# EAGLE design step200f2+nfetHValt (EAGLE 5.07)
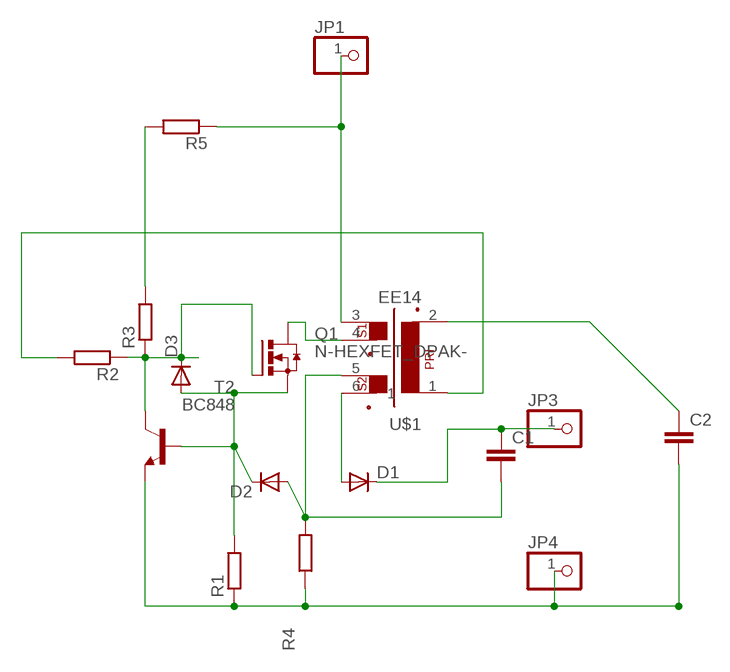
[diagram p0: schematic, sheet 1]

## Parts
C1  C-EU025-025X050  [C025-025X050]
C2  C-EUC0805  [C0805]
D1  DIODE-SMA-DO214  [SMA-DO214AC]
D2  DIODE-MINIMELF  [MINIMELF]
D3  DIODE-MINIMELF  [MINIMELF]
JP1  PINHD-1X11MM6  [1X1MM8]
JP3  PINHD-1X11MM6  [1X1MM8]
JP4  PINHD-1X11MM6  [1X1MM8]
Q1  N-HEXFET_DPAK-  [TO252]
R1  R-EU_R1206  [R1206]
R2  R-EU_R0805  [R0805]
R3  R-EU_R1206  [R1206]
R4  R-EU_R0805  [R0805]
R5  R-EU_R1206  [R1206]
T2  BC848  [SOT23]
U$1  EE14  [EE14]

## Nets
A: D1.A U$1.6
B1C2: D3.C Q1.1(G) R2.1 R3.1 T2.C
C1: Q1.3(D) U$1.4
EB: D2.C D3.A Q1.2(S) R1.2 T2.B
N$1: R3.2 R5.2
N$4: R2.2 U$1.1
N$6: C2.1 U$1.2
NDOT: C1.2 D2.A R4.2 U$1.5
V+: JP1.1 R5.1 U$1.3
V-: C2.2 JP4.1 R1.1 R4.1 T2.E
VOUT+: C1.1 D1.K(C) JP3.1

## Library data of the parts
C1 C2 = rcl:C-EU: CAPACITOR, European symbol
D1-D3 = diode:DIODE-: DIODE
JP1 JP3 JP4 = pinhead:PINHD-1X1: PIN HEADER
Q1 = transistor-power:N-HEXFET_?-*: HEXFET® Power MOSFET
R1-R5 = rcl:R-EU_: RESISTOR, European symbol
T2 = transistor:BC848: NPN TRANSISTOR
U$1 = trafo:EE14

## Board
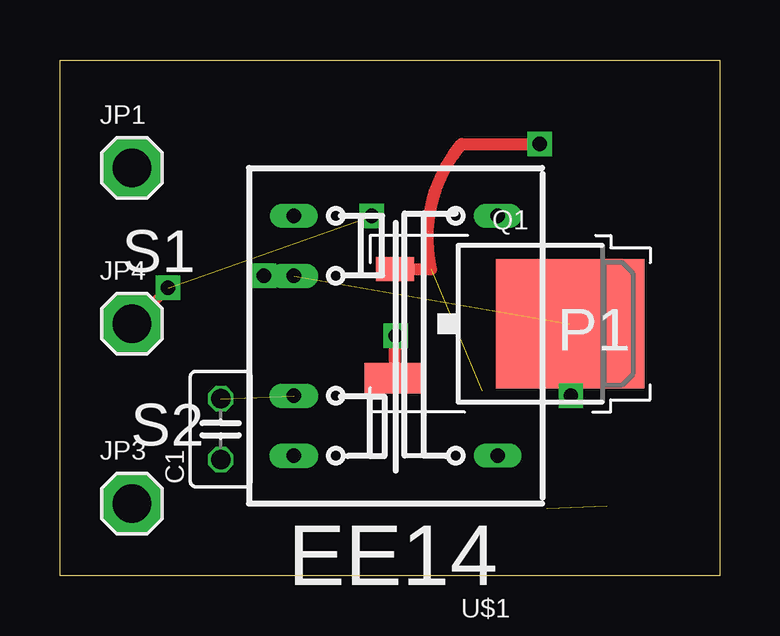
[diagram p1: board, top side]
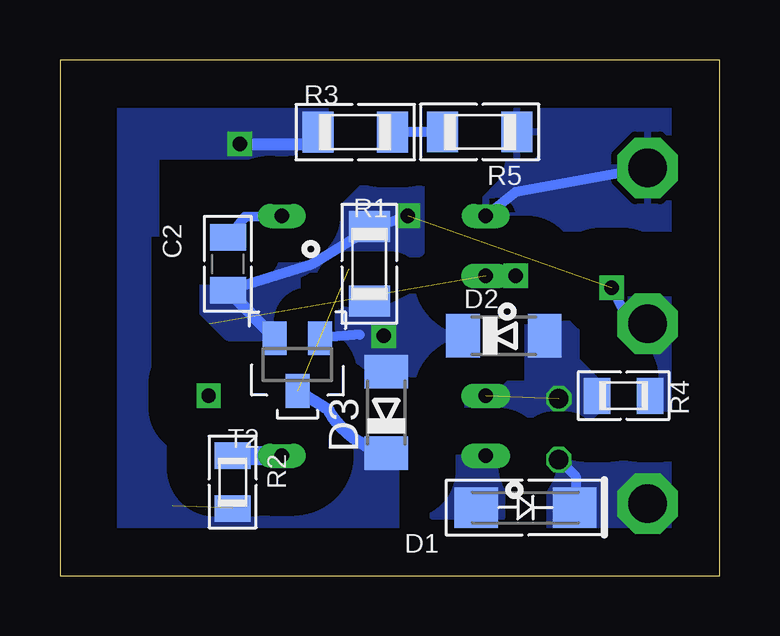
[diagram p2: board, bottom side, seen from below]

Size 27.5 x 21.5 mm. Coordinates in mm from the lower left corner, seen from the top.
Outline: 0,21.5 27.5,21.5 27.5,0 0,0 0,21.5
Copper layers (1*16): Top 0.035mm / dielectric 1.5mm / Bottom 0.035mm
Design rules "default *": minimum track width 10mil, minimum drill 20mil, track to track 8mil, track to pad 8mil, pad to pad 8mil, via to via 8mil, smd to smd 8mil, copper to edge 40mil, drill to drill 8mil, minimum pad ring 1mil, minimum via ring 8mil, stop-mask expansion 4mil, vias tented up to drill 0mil, thermal gap 10mil

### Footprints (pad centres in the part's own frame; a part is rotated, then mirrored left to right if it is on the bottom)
C025-025X050 = drill 0.813 octagon: 1 -1.27,0; 2 1.27,0
C0805 = smd 1.1 x 1.5: 1 -1.1,0; 2 1.1,0
SMA-DO214AC = smd 1.8 x 1.7: A 2.05,-0.127; K -2.05,-0.127
MINIMELF = smd 1.4 x 1.8: A 1.7,0; C -1.7,0
1X1MM8 = drill 1.6 pad 2.54 octagon: 1 0,0
TO252 = smd 1 x 1.6: 1 -2.28,-3.53 | smd 1.27 x 2.54: 2 2.28,-3.53 | smd 5.4 x 6.2: 3 0,3.77
R1206 = smd 1.3 x 1.7: 1 -1.55,0; 2 1.55,0
R0805 = smd 1.1 x 1.5: 1 -1.1,0; 2 1.1,0
SOT23 = smd 1 x 1.4: B -0.95,-1.1; C 0,1.1; E 0.95,-1.1
EE14 = drill 0.6 pad 1 long: 1 4.25,-5; 2 4.25,5; 3 -4.25,5 | drill 0.6 pad 1.016 long: 4 -4.25,2.5; 5 -4.25,-2.5; 6 -4.25,-5

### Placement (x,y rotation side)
C1  6.7,6.11 90 top
C2  20.5,13 270 bottom
D1  8.1,2.71 180 bottom
D2  9,10 0 bottom
D3  13.9,6.8 90 bottom
JP1  3,17 0 top
JP3  3,3 0 top
JP4  3,10.5 0 top
Q1  17.5,10.5 270 top
R1  14.6,13 270 bottom
R2  20.3,3.9 90 bottom
R3  15.19,18.49 0 bottom
R4  4,7.5 180 bottom
R5  10,18.5 180 bottom
T2  17.6,8.8 180 bottom
U$1  14,10 0 top

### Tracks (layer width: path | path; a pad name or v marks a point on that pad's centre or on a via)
A
  pour Bottom (isolate 2, rank 3, no thermals): 9,5 11.5,5 12,4.5 12,2.5 9,2.5
B1C2  (via drill 0.6)  (2 unrouted)
  Top 0.5: Q1.1 15.47,12.78 arc-52 16.74,17.99 v19.99,17.99 v20,18
  Bottom 0.5: v20,18 16.75,18 R3.1 | T2.C 16.3,6.9 arc-48 D3.C
  pour Bottom (isolate 2, rank 3, no thermals): 15.5,19.5 25,19.5 25,1 13.5,1 13.5,5.5 15,5.5 19.5,3.5 22.5,4.5 22.5,5.5 23.5,6.5 23.5,17.5 15.5,17.5
C1  (via drill 0.6)  (1 unrouted)
  Top 0.406: v21.3,7.5 Q1.3 | v8.5,12.5 9,12.5
  Bottom 0.406: v21.3,7.5 21,7.5 | U$1.4 v8.5,12.5
EB  (via drill 0.6)
  Top 0.5: Q1.2 13.97,9.47 v14,10
  Bottom 0.406: 15,10.05 T2.B
  Bottom 0.5: v14,10 14,10.05
  pour Bottom (isolate 2, no thermals): 12,12 14,11 16.5,11 16.5,9.5 15,8.5 11.5,8.5 10.5,9 10.5,11
N$1
  Bottom 0.406: R5.2 R3.2
N$4
  Bottom 0.8: U$1.1 R2.2
N$6
  Bottom 0.406: C2.1 19.8,14.95 U$1.2
NDOT  (1 unrouted)
  pour Bottom (isolate 1.5, rank 3, no thermals): 5,8 5,7 5.5,6.5 10,6.5 10.5,7 10.5,7.5 10,8 8,8 8,10.5 6,10.5 6,9
V+
  Bottom 0.406: U$1.3 8.5,16 JP1.1
  pour Bottom (isolate 2, rank 4): 1,19.5 9.5,19.5 9.1,17.4 9.1,16.4 10,15.5 10.5,14.5 1,14.5
V-  (via drill 0.6)  (1 unrouted)
  Top 0.406: JP4.1 v4.5,12
  Bottom 0.406: v13,15 14,14.65 R1.1 14.45,14.55 17,13 C2.2 | v4.5,12 4,11
  Bottom 0.5: T2.E C2.2
  pour Bottom (isolate 2, rank 4, no thermals): 1,11.5 4.5,11.5 5,11 5,9.5 4,8.5 4,7 1,7
  pour Bottom (isolate 1.422, rank 2, no thermals): 12.5,16.5 14.5,16.5 17,14 20,14 21.5,12.5 21.5,11 20.5,10 18,10 18,11 17.5,11.5 16.5,11.5 14.5,13.5 12.5,13.5 12.5,16
VOUT+
  Bottom 0.406: C1.1 6,4.13 6,3.5
  pour Bottom (isolate 2, rank 3, no thermals): 1,5 7,5 7.5,4.5 7.5,1 1,1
